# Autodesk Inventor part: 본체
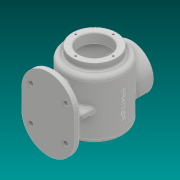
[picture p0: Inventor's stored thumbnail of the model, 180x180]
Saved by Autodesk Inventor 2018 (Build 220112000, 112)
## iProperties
Created: 2023-01
Part Number: 본체
Material: 일반
Document SubType Name: Modeling
Designer: 강의실01
Density: 1 g/cm^3
Appearance: 기본값
Author: 강의실01
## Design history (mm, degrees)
sketch "스케치1"
  geometry: L1 (46, -63)-(-46, -63); L2 (-46, -63)-(-46, 63); L3 (-46, 63)-(46, 63); L4 (46, 63)-(46, -63); L5 (46, -63)-(-46, 63); L6 (-46, -63)-(46, 63); 1 further point
  constraints: 12 end point, 2 midpoint, 2 parallel, 1 horizontal, 1 perpendicular
  dimensions: "d0" = 92 distance of L2.end L3.end; "d1" = 126 distance of L1.end L2.end
extrude "돌출1" new body sketch "스케치1" distance "d2" = 10; taper "d3" = 0 deg
sketch "스케치2"
  geometry: L1 (0, 63)-(0, -63) reference; L2 (107, 63)-(107, 46); L3 (107, 46)-(125, 46); L4 (118, 51)-(130, 51); L5 (130, 51)-(130, -48.087); L6 (125, 46)-(125, -44.83); L7 (118, 63)-(118, 51); L8 (80, 59)-(80, -59); L9 (107, 63)-(118, 63); A1 r 120 centre (80, 61) between (80, -59) and (130, -48.087); A2 r 115 centre (80, 61) between (80, -54) and (125, -44.83); 3 further points
  constraints: 16 end point, 4 point on circle, 3 perpendicular, 3 vertical, 2 centre point, 2 midpoint, 1 horizontal, 1 horizontal alignment, 1 point on line
  dimensions: "d20" = 5 distance between parallel lines of L6 L5; "d21" = 54 diameter of L2 L8; "d22" = 76 diameter of L7 L8; "d23" = 90 diameter of L6 L8; "d26" = 100 diameter of L5 L8 (derived); "d120" = 59 vertical distance of L8.end point (0, 0); "d122" = 160 diameter of L1 L8; "d124" = 17 distance between parallel lines of L3 L9; "d125" = 5 distance between parallel lines of L3 L4; "d126" = 120 radius of A1; "d127" = 5 radial gap between concentric circles of A1 A2; "d128" = 122 distance from line of L8.end L9 (derived); "d129" = 80 distance from line of A1.centre L1; "d133" = 51 distance from line of point (80, 0) L4
revolve "회전1" sketch "스케치2" stored, may be unused: angle "d39" = 90 deg
node "작업 평면1"
sketch "스케치3"
  geometry: L1 (-50, 51)-(50, 51) reference; C1 r 38 at (0, 0); 1 further point
  constraints: 1 centre point
  dimensions: "d41" = 76 diameter of C1; "d42" = 51 distance from line of L1 C1.centre; "d43" = 71.42129 distance of L1.end C1.centre
extrude "돌출2" join sketch "스케치3" stored distance "d44" = 10; taper "d45" = 0 deg
hole "구멍1" diameter "d48" = 54; stored, may be unused: countersink angle "d52" = 90 deg, drill point angle "d54" = 0 deg; dims "d46" = 10, "d47" = 10, "d49" = 6, "d50" = 4, "d51" = 2, "d53" = 30
sketch "스케치4" dims "d55" = 65
  geometry: L1 (50, -51)-(-50, -51) reference; C1 r 27 at (0, 0) reference; 3 further points
  constraints: 1 coincident, 1 vertical alignment, 2 other
  dimensions: "d56" = 83.5 distance from line of L1 point (0, 32.5)
hole "구멍2" sketch "스케치4" at (0, 32.5) diameter "d57" = 3.242; stored, may be unused: countersink angle "d61" = 90 deg, drill point angle "d63" = 118 deg; dims "d58" = 8, "d59" = 4, "d60" = 2, "d62" = 10
sketch "스케치5" dims "d67" = 65
  geometry: L1 (46, -80)-(-46, -80) reference; 3 further points
  constraints: 1 horizontal alignment, 2 other
  dimensions: "d68" = 80 distance from line of L1 point (-32.5, 0); "d69" = 80 distance from line of point (0, 0) L1; "d70" = 92.28218 distance of L1.start point (0, 0)
hole "구멍3" sketch "스케치5" at (-32.5, 0) diameter "d71" = 3.242; stored, may be unused: countersink angle "d75" = 90 deg, drill point angle "d77" = 118 deg; dims "d72" = 8, "d73" = 4, "d74" = 2, "d76" = 10
sketch "스케치6"
  geometry: L1 (46, 10)-(-46, 10) reference; L2 (-35, 10)-(-35, 44.293); L3 (35, 44.293)-(35, 10); A1 r 50 centre (0, 80) between (-35, 44.293) and (35, 44.293) reference; 1 further point
  constraints: 4 end point, 2 point on circle, 2 point on line, 1 perpendicular, 1 vertical
  dimensions: "d81" = 35 horizontal distance of L3.end point (0, 0); "d82" = 70 distance of L2.start L3.end
extrude "돌출3" join sketch "스케치6" stored distance "d83" = 10; taper "d84" = 0 deg
sketch "스케치7"
  geometry: L1 (10, -63)-(10, 63) reference; L2 (10, -40)-(30, -34.641); L3 (30, 51)-(30, -48.087) reference; 1 further point
  constraints: 2 end point, 2 point on line
  dimensions: "d85" = 105 deg angle of L2 L1; "d86" = 40 vertical distance of point (0, 0) L2.start
feature "리브1" sketch "스케치7" dims "d87" = 1, "d88" = 10, "d89" = 0, "d90" = 0, "d91" = 1, "d92" = 1
fillet "모깎기1" dims "d93" = 46, "d108" = 8
sketch "스케치8"
  geometry: 3 further points
  dimensions: "d97" = 30 horizontal distance of point (0, 0) point (-30, -30); "d98" = 60 distance of point (30, -30) point (-30, -30); "d99" = 30 horizontal distance of point (-30, -30) point (0, 0); "d100" = 30 horizontal distance of point (30, -30) point (0, 0)
hole "구멍4" sketch "스케치8" at (-30, -30), (30, -30) diameter "d101" = 9; stored, may be unused: countersink angle "d105" = 90 deg, drill point angle "d107" = 0 deg; dims "d102" = 8, "d103" = 4, "d104" = 2, "d106" = 10
node "작업 평면2"
sketch "스케치9"
  geometry: L1 (42, 63)-(118, 63) reference; 2 further points
  constraints: 1 other
  dimensions: "d110" = 80 distance of point (0, 0) point (80, 0); "d111" = 63 distance from line of L1 point (80, 0)
feature "엠보싱1" sketch "스케치9" dims "d0" = 92, "d1" = 126, "d112" = 0.5, "d113" = 0
chamfer "모따기1" distance "d114" = 1; stored, may be unused: second distance "d115" = 2, angle "d116" = 45 deg
fillet "모깎기2" dims "d117" = 3
fillet "모깎기3" dims "d118" = 3
chamfer "모따기2" distance "d135" = 1; stored, may be unused: second distance "d136" = 2, angle "d137" = 45 deg
node "솔리드1"
pattern_circular "원형 패턴1" dims angle "d65" = 360 deg
pattern_circular "원형 패턴2" dims angle "d79" = 360 deg
mirror "미러1"
mirror "미러2"
other parameters: "d13" = 76, "d40" = 144
